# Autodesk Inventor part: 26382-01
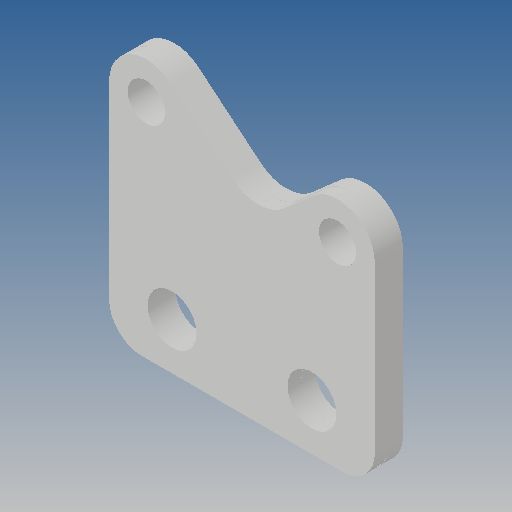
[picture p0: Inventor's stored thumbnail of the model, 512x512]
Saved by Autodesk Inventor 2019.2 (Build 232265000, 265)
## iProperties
Created: 2012-09
Part Number: 26382-01
Material: Ogólny
Document SubType Name: Modeling
Designer: CADENGINEERING4
Density: 1 g/cm^3
Appearance: Domyślna
Author: CADENGINEERING4
Revision Number: ÈÎºÎ
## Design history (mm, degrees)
feature "À­Éì1"
feature "¾µÏò1"
node "Bryła1"
node "Bryła2"
